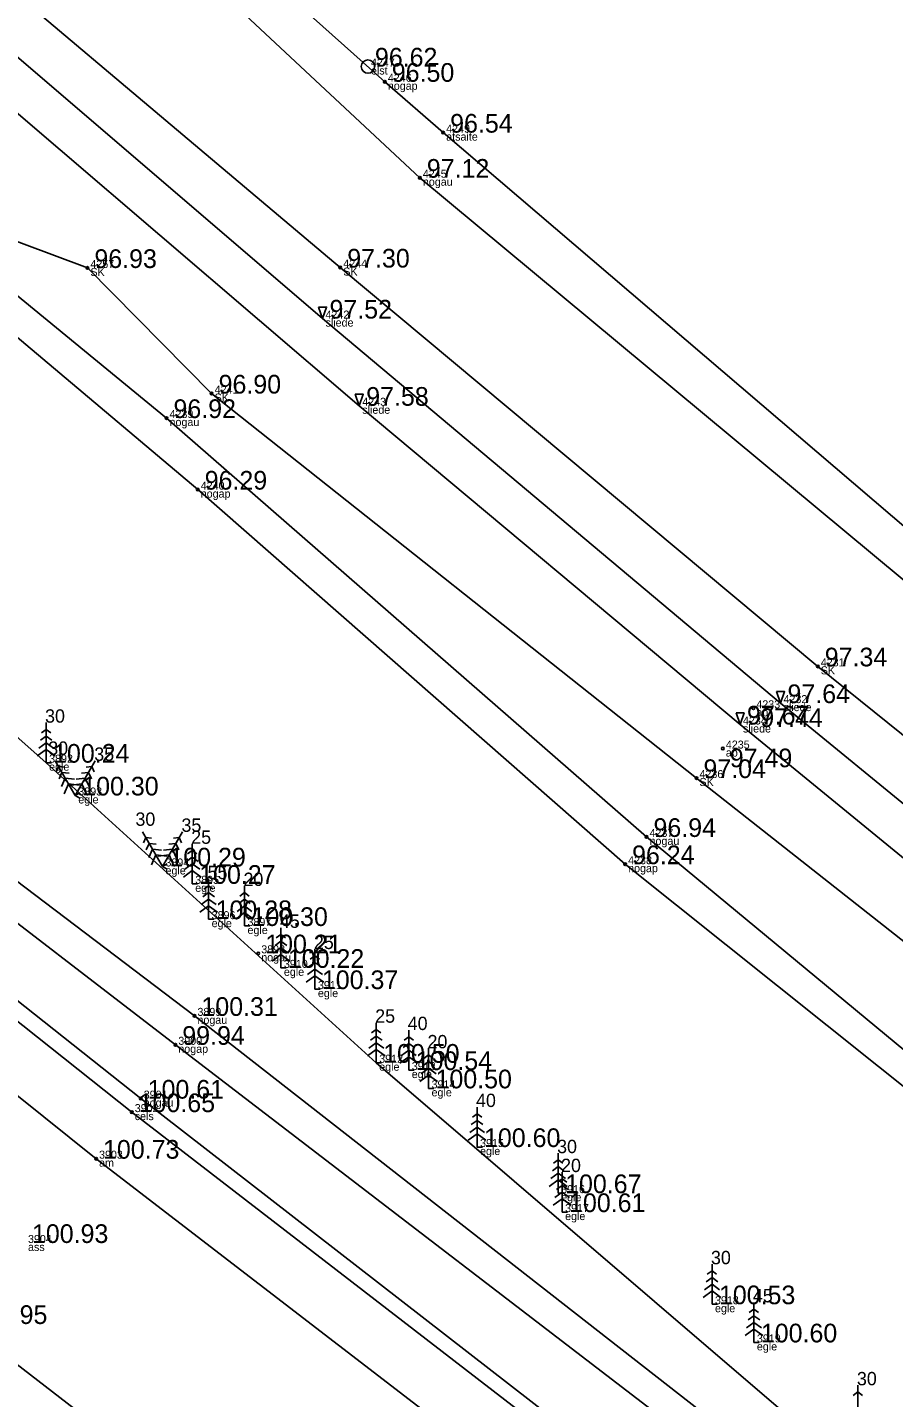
# Model space of a CAD drawing. Extents: x 614911 to 615803, y 262110 to 264311.
# Drawn here: x 615690.4 to 615722.9, y 264108 to 264159.4 of the extents above; entities that cross this region are included whole.
import ezdxf

# ---------------------------------------------------------------- set-up
doc = ezdxf.new("R2010")
doc.units = 0
for name, color, linetype in [('Level 1', 7, 'Continuous'), ('Level 18', 7, 'Continuous'), ('Level 31', 7, 'Continuous'), ('Level 37', 7, 'Continuous'), ('Level 53', 7, 'Continuous'), ('Level 54', 7, 'Continuous'), ('Level 57', 7, 'Continuous'), ('Level 58', 7, 'Continuous')]:
    doc.layers.add(name, color=color, linetype=linetype)

msp = doc.modelspace()

# ---------------------------------------------------------------- linework, layer by layer
at = {"layer": 'Level 1'}
for p, q in [((615691.136, 264133.05), (615690.96, 264132.922)), ((615691.136, 264133.3), (615691.136, 264131.8)), ((615691.136, 264133.05), (615691.31, 264132.922)), ((615691.136, 264132.55), (615690.858, 264132.346)), ((615691.136, 264132.8), (615690.92, 264132.642)), ((615691.136, 264132.8), (615691.352, 264132.642)), ((615691.136, 264132.55), (615691.414, 264132.346)), ((615691.136, 264132.3), (615690.804, 264132.056)), ((615691.136, 264132.3), (615691.47, 264132.056)), ((615691.48, 264131.87), (615692.23, 264130.571)), ((615692.98, 264131.87), (615692.23, 264130.571)), ((615691.136, 264131.8), (615691.336, 264131.8)), ((615691.605, 264131.654), (615691.517, 264131.455)), ((615691.605, 264131.654), (615691.82, 264131.63)), ((615691.73, 264131.437), (615691.622, 264131.192)), ((615691.73, 264131.437), (615691.996, 264131.408)), ((615692.73, 264131.437), (615692.464, 264131.408)), ((615692.855, 264131.654), (615692.639, 264131.631)), ((615692.73, 264131.437), (615692.838, 264131.192)), ((615692.855, 264131.654), (615692.942, 264131.456)), ((615691.855, 264131.221), (615691.716, 264130.905)), ((615691.98, 264131.004), (615691.814, 264130.627)), ((615691.855, 264131.221), (615692.198, 264131.183)), ((615691.98, 264131.004), (615692.391, 264130.96)), ((615692.48, 264131.004), (615692.07, 264130.959)), ((615692.605, 264131.221), (615692.262, 264131.183)), ((615692.48, 264131.004), (615692.647, 264130.626)), ((615692.605, 264131.221), (615692.744, 264130.905)), ((615692.23, 264130.571), (615692.403, 264130.671)), ((615692.23, 264130.571), (615692.403, 264130.471)), ((615694.748, 264129.209), (615695.498, 264127.91)), ((615694.873, 264128.993), (615694.785, 264128.794)), ((615694.873, 264128.993), (615695.088, 264128.969)), ((615694.998, 264128.776), (615694.89, 264128.531)), ((615694.998, 264128.776), (615695.264, 264128.747)), ((615696.248, 264129.209), (615695.498, 264127.91)), ((615695.998, 264128.776), (615695.732, 264128.747)), ((615696.123, 264128.993), (615695.907, 264128.97)), ((615695.998, 264128.776), (615696.106, 264128.531)), ((615696.123, 264128.993), (615696.21, 264128.795)), ((615696.614, 264128.759), (615696.614, 264127.259)), ((615695.123, 264128.56), (615694.984, 264128.244)), ((615695.248, 264128.343), (615695.082, 264127.966)), ((615695.123, 264128.56), (615695.466, 264128.522)), ((615695.248, 264128.343), (615695.659, 264128.299)), ((615695.748, 264128.343), (615695.338, 264128.298)), ((615695.873, 264128.56), (615695.53, 264128.522)), ((615695.748, 264128.343), (615695.915, 264127.965)), ((615695.873, 264128.56), (615696.012, 264128.244)), ((615696.614, 264128.259), (615696.398, 264128.101)), ((615696.614, 264128.509), (615696.438, 264128.381)), ((615696.614, 264128.509), (615696.788, 264128.381)), ((615696.614, 264128.259), (615696.83, 264128.101)), ((615695.498, 264127.91), (615695.671, 264128.01)), ((615695.498, 264127.91), (615695.671, 264127.81)), ((615696.614, 264127.759), (615696.282, 264127.515)), ((615696.614, 264128.009), (615696.336, 264127.805)), ((615696.614, 264128.009), (615696.892, 264127.805)), ((615696.614, 264127.759), (615696.948, 264127.515)), ((615696.614, 264127.259), (615696.814, 264127.259)), ((615697.228, 264127.435), (615697.228, 264125.935)), ((615697.228, 264126.935), (615697.012, 264126.777)), ((615697.228, 264127.185), (615697.052, 264127.057)), ((615697.228, 264127.185), (615697.402, 264127.057)), ((615697.228, 264126.935), (615697.444, 264126.777)), ((615698.573, 264126.929), (615698.397, 264126.801)), ((615698.573, 264127.179), (615698.573, 264125.679)), ((615698.573, 264126.929), (615698.747, 264126.801)), ((615697.228, 264126.435), (615696.896, 264126.191)), ((615697.228, 264126.685), (615696.95, 264126.481)), ((615697.228, 264126.685), (615697.506, 264126.481)), ((615697.228, 264126.435), (615697.562, 264126.191)), ((615698.573, 264126.179), (615698.241, 264125.935)), ((615698.573, 264126.429), (615698.295, 264126.225)), ((615698.573, 264126.679), (615698.357, 264126.521)), ((615698.573, 264126.679), (615698.789, 264126.521)), ((615698.573, 264126.429), (615698.851, 264126.225)), ((615698.573, 264126.179), (615698.907, 264125.935)), ((615697.228, 264125.935), (615697.428, 264125.935)), ((615698.573, 264125.679), (615698.773, 264125.679)), ((615699.938, 264125.36), (615699.762, 264125.232)), ((615699.938, 264125.61), (615699.938, 264124.11)), ((615699.938, 264125.36), (615700.112, 264125.232)), ((615699.938, 264124.86), (615699.66, 264124.656)), ((615699.938, 264125.11), (615699.722, 264124.952)), ((615699.938, 264125.11), (615700.154, 264124.952)), ((615699.938, 264124.86), (615700.216, 264124.656)), ((615701.213, 264124.814), (615701.213, 264123.314)), ((615699.938, 264124.61), (615699.606, 264124.366)), ((615699.938, 264124.61), (615700.272, 264124.366)), ((615701.213, 264124.314), (615700.997, 264124.156)), ((615701.213, 264124.564), (615701.037, 264124.436)), ((615701.213, 264124.564), (615701.387, 264124.436)), ((615701.213, 264124.314), (615701.429, 264124.156)), ((615699.938, 264124.11), (615700.138, 264124.11)), ((615701.213, 264123.814), (615700.881, 264123.57)), ((615701.213, 264124.064), (615700.935, 264123.86)), ((615701.213, 264124.064), (615701.491, 264123.86)), ((615701.213, 264123.814), (615701.547, 264123.57)), ((615701.213, 264123.314), (615701.413, 264123.314)), ((615703.511, 264121.554), (615703.295, 264121.396)), ((615703.511, 264121.804), (615703.335, 264121.676)), ((615703.511, 264122.054), (615703.511, 264120.554)), ((615703.511, 264121.804), (615703.685, 264121.676)), ((615703.511, 264121.554), (615703.727, 264121.396)), ((615704.73, 264121.779), (615704.73, 264120.279)), ((615703.511, 264121.054), (615703.179, 264120.81)), ((615703.511, 264121.304), (615703.233, 264121.1)), ((615703.511, 264121.304), (615703.789, 264121.1)), ((615703.511, 264121.054), (615703.845, 264120.81)), ((615704.73, 264121.279), (615704.514, 264121.121)), ((615704.73, 264121.529), (615704.554, 264121.401)), ((615704.73, 264121.529), (615704.904, 264121.401)), ((615704.73, 264121.279), (615704.946, 264121.121)), ((615705.473, 264121.094), (615705.473, 264119.594)), ((615703.511, 264120.554), (615703.711, 264120.554)), ((615704.73, 264120.779), (615704.398, 264120.535)), ((615704.73, 264121.029), (615704.452, 264120.825)), ((615704.73, 264121.029), (615705.008, 264120.825)), ((615704.73, 264120.779), (615705.064, 264120.535)), ((615705.473, 264120.594), (615705.257, 264120.436)), ((615705.473, 264120.844), (615705.297, 264120.716)), ((615705.473, 264120.844), (615705.647, 264120.716)), ((615705.473, 264120.594), (615705.689, 264120.436)), ((615704.73, 264120.279), (615704.93, 264120.279)), ((615705.473, 264120.094), (615705.141, 264119.85)), ((615705.473, 264120.344), (615705.195, 264120.14)), ((615705.473, 264120.344), (615705.751, 264120.14)), ((615705.473, 264120.094), (615705.807, 264119.85)), ((615705.473, 264119.594), (615705.673, 264119.594)), ((615707.291, 264118.644), (615707.115, 264118.516)), ((615707.291, 264118.894), (615707.291, 264117.394)), ((615707.291, 264118.644), (615707.465, 264118.516)), ((615707.291, 264118.144), (615707.013, 264117.94)), ((615707.291, 264118.394), (615707.075, 264118.236)), ((615707.291, 264118.394), (615707.507, 264118.236)), ((615707.291, 264118.144), (615707.569, 264117.94)), ((615707.291, 264117.894), (615706.959, 264117.65)), ((615707.291, 264117.894), (615707.625, 264117.65)), ((615707.291, 264117.394), (615707.491, 264117.394)), ((615710.331, 264117.165), (615710.331, 264115.665)), ((615710.331, 264116.665), (615710.115, 264116.507)), ((615710.331, 264116.915), (615710.155, 264116.787)), ((615710.331, 264116.915), (615710.505, 264116.787)), ((615710.331, 264116.665), (615710.547, 264116.507)), ((615710.479, 264116.456), (615710.479, 264114.956)), ((615710.331, 264116.165), (615709.999, 264115.921)), ((615710.331, 264116.415), (615710.053, 264116.211)), ((615710.479, 264115.956), (615710.263, 264115.798)), ((615710.479, 264116.206), (615710.303, 264116.078)), ((615710.331, 264116.415), (615710.609, 264116.211)), ((615710.331, 264116.165), (615710.665, 264115.921)), ((615710.479, 264116.206), (615710.653, 264116.078)), ((615710.479, 264115.956), (615710.695, 264115.798)), ((615710.479, 264115.456), (615710.147, 264115.212)), ((615710.479, 264115.706), (615710.201, 264115.502)), ((615710.331, 264115.665), (615710.531, 264115.665)), ((615710.479, 264115.706), (615710.757, 264115.502)), ((615710.479, 264115.456), (615710.813, 264115.212)), ((615710.479, 264114.956), (615710.679, 264114.956)), ((615716.098, 264113.002), (615716.098, 264111.502)), ((615716.098, 264112.502), (615715.882, 264112.344)), ((615716.098, 264112.752), (615715.922, 264112.624)), ((615716.098, 264112.752), (615716.272, 264112.624)), ((615716.098, 264112.502), (615716.314, 264112.344)), ((615716.098, 264112.002), (615715.766, 264111.758)), ((615716.098, 264112.252), (615715.82, 264112.048)), ((615716.098, 264112.252), (615716.376, 264112.048)), ((615716.098, 264112.002), (615716.432, 264111.758)), ((615716.098, 264111.502), (615716.298, 264111.502)), ((615717.669, 264111.322), (615717.493, 264111.194)), ((615717.669, 264111.572), (615717.669, 264110.072)), ((615717.669, 264111.322), (615717.843, 264111.194)), ((615717.669, 264110.822), (615717.391, 264110.618)), ((615717.669, 264111.072), (615717.453, 264110.914)), ((615717.669, 264111.072), (615717.885, 264110.914)), ((615717.669, 264110.822), (615717.947, 264110.618)), ((615717.669, 264110.572), (615717.337, 264110.328)), ((615717.669, 264110.572), (615718.003, 264110.328)), ((615717.669, 264110.072), (615717.869, 264110.072)), ((615721.57, 264108.214), (615721.394, 264108.086)), ((615721.57, 264108.464), (615721.57, 264106.964)), ((615721.57, 264108.214), (615721.744, 264108.086))]:
    msp.add_line(p, q, dxfattribs=at)
at = {"layer": 'Level 18'}
msp.add_circle((615703.201, 264157.893), 0.25, dxfattribs=at)
at = {"layer": 'Level 31'}
for points in [[(615550.836, 264303.699), (615565.947, 264286.87), (615580.435, 264272.627), (615620.447, 264233.205), (615638.898, 264215.233), (615657.591, 264198.466), (615675.473, 264182.627), (615703.834, 264157.321), (615706.022, 264155.415), (615724.24, 264139.85), (615743.993, 264123.553), (615763.286, 264108.956)], [(615762.569, 264108.432), (615743.376, 264122.276), (615723.221, 264138.687), (615705.147, 264153.725), (615674.877, 264181.955), (615656.951, 264197.747), (615637.976, 264214.014), (615619.221, 264231.816), (615602.006, 264248.823), (615581.186, 264269.584), (615564.897, 264285.757), (615549.808, 264302.584)], [(615540.752, 264293.153), (615554.871, 264276.489), (615571.152, 264259.742), (615591.296, 264239.745), (615608.637, 264222.837), (615628.706, 264203.767), (615646.768, 264187.421), (615664.713, 264171.246), (615679.702, 264157.791), (615695.65, 264144.718), (615713.644, 264129.017), (615734.176, 264112.026), (615754.636, 264096.634)], [(615753.478, 264095.562), (615733.7, 264111.337), (615712.842, 264127.996), (615696.82, 264142.035), (615679.383, 264156.731), (615663.464, 264170.411), (615645.861, 264186.034), (615627.735, 264202.684), (615607.548, 264221.434), (615590.341, 264238.61), (615571.816, 264257.419), (615555.77, 264271.235), (615553.667, 264275.682), (615546.609, 264281.236), (615539.858, 264291.16)], [(615744.764, 264081.359), (615732.887, 264089.943), (615715.889, 264102.764), (615694.682, 264119.208), (615676.974, 264133.244), (615650.72, 264155.552), (615629.606, 264174.135), (615612.305, 264190.628), (615596.307, 264206.969), (615581.341, 264223.238), (615571.304, 264233.709), (615558.243, 264246.987), (615542.242, 264265.322), (615529.994, 264284)], [(615573.297, 264235.218), (615582.765, 264223.901), (615598.169, 264208.795), (615613.95, 264192.439), (615631.402, 264176.068), (615651.799, 264157.165), (615678.305, 264134.819), (615695.98, 264121.225), (615717.243, 264104.936), (615734.373, 264091.846), (615746.465, 264082.76)], [(615748.571, 264085.022), (615736.423, 264094.22), (615719.121, 264107.166), (615703.511, 264120.554), (615691.136, 264131.8), (615678.521, 264143.006), (615664.052, 264155.366), (615649.085, 264167.868)], [(615652.699, 264158.282), (615678.791, 264135.883), (615696.697, 264122.31), (615717.87, 264105.783), (615735.585, 264093.051), (615747.497, 264083.99)]]:
    msp.add_lwpolyline(points, dxfattribs=at)
at = {"layer": 'Level 37'}
for points in [[(615761.079, 264103.167), (615740.608, 264118.87), (615720.064, 264135.41), (615702.164, 264150.358), (615683.412, 264166.162), (615670.618, 264177.317), (615652.713, 264193.863), (615634.786, 264210.699), (615620.941, 264223.967), (615615.966, 264228.972), (615599.176, 264245.886), (615578.012, 264266.798), (615562.423, 264283.045), (615547.324, 264299.857)], [(615759.565, 264101.106), (615739.143, 264117.266), (615718.667, 264134.033), (615701.498, 264148.445), (615682.756, 264164.518), (615669.543, 264176.126), (615651.347, 264192.511), (615633.272, 264209.191), (615614.204, 264227.4), (615597.285, 264244.019), (615576.358, 264265.082), (615560.633, 264281.446), (615545.346, 264297.738)], [(615544.24, 264296.658), (615559.48, 264280.438), (615575.312, 264263.924), (615595.914, 264243.146), (615613.083, 264226.335), (615632.332, 264207.923), (615650.408, 264191.231), (615668.49, 264174.989), (615684.179, 264161.185), (615702.875, 264145.178), (615717.148, 264133.231), (615738.189, 264116.022), (615758.45, 264099.985)], [(615540.752, 264293.153), (615550.108, 264282.114), (615552.773, 264283.226), (615557.41, 264278.457), (615573.64, 264261.965), (615593.655, 264241.56), (615611.026, 264224.494), (615630.543, 264205.827), (615648.416, 264189.194), (615666.454, 264173.12), (615670.636, 264169.646), (615672.409, 264164.575), (615679.702, 264157.791), (615684.212, 264153.509), (615692.685, 264150.342), (615697.341, 264145.636), (615715.517, 264131.224), (615736.783, 264114.465), (615756.444, 264098.349)], [(615526.871, 264279.709), (615557.508, 264246.916), (615570.946, 264232.844), (615580.588, 264222.695), (615595.945, 264206.676), (615612.011, 264190.126), (615629.214, 264173.64), (615650.344, 264154.99), (615676.59, 264132.802), (615694.345, 264118.703), (615715.543, 264102.359), (615732.654, 264089.574), (615744.576, 264080.858)], [(615743.178, 264079.076), (615731.345, 264087.792), (615714.316, 264100.575), (615693.008, 264116.957), (615675.219, 264131.222), (615649.561, 264152.667), (615627.765, 264171.974), (615611.182, 264188.292), (615594.351, 264205.525), (615579.137, 264221.33), (615569.398, 264231.353), (615556.134, 264245.272), (615540.03, 264262.148), (615525.148, 264277.969)], [(615625.063, 264106.562), (615623.229, 264104.588), (615622.747, 264105.634), (615621.37, 264105.71), (615619.131, 264107.71), (615616.734, 264111.901), (615616.748, 264121.153), (615617.254, 264127.034), (615619.687, 264135.318), (615625.708, 264142.666), (615632.784, 264145.968), (615640.605, 264144.932), (615648.422, 264143.136), (615670.375, 264124.985), (615688.06, 264110.762), (615709.564, 264094.167), (615727.03, 264081.038), (615738.779, 264072.364)]]:
    msp.add_lwpolyline(points, dxfattribs=at)
at = {"layer": 'Level 57'}
for centre in [(615703.834, 264157.321), (615706.022, 264155.415), (615705.147, 264153.725), (615692.685, 264150.342), (615702.164, 264150.358), (615697.341, 264145.636), (615695.65, 264144.718), (615696.82, 264142.035), (615720.064, 264135.41), (615717.648, 264133.838), (615716.505, 264132.329), (615715.517, 264131.224), (615713.644, 264129.017), (615712.842, 264127.996), (615699.089, 264124.654), (615696.697, 264122.31), (615695.98, 264121.225), (615694.682, 264119.208), (615694.345, 264118.703), (615693.008, 264116.957)]:
    msp.add_circle(centre, 0.05, dxfattribs=at)
at = {"layer": 'Level 58'}
for points in [[(615701.348, 264148.879), (615701.648, 264148.879), (615701.498, 264148.446)], [(615702.725, 264145.611), (615703.025, 264145.611), (615702.875, 264145.178)], [(615718.517, 264134.466), (615718.817, 264134.466), (615718.667, 264134.033)], [(615716.998, 264133.664), (615717.298, 264133.664), (615717.148, 264133.231)]]:
    msp.add_lwpolyline(points, close=True, dxfattribs=at)
for centre in [(615703.834, 264157.321), (615706.022, 264155.415), (615705.147, 264153.725), (615692.685, 264150.342), (615702.164, 264150.358), (615697.341, 264145.636), (615695.65, 264144.718), (615696.82, 264142.035), (615720.064, 264135.41), (615717.648, 264133.838), (615716.505, 264132.329), (615715.517, 264131.224), (615713.644, 264129.017), (615712.842, 264127.996), (615699.089, 264124.654), (615696.697, 264122.31), (615695.98, 264121.225), (615694.682, 264119.208), (615694.345, 264118.703), (615693.008, 264116.957)]:
    msp.add_circle(centre, 0.05, dxfattribs=at)

# ---------------------------------------------------------------- texts
at = {"layer": 'Level 1'}
for s, p in [(' 30', (615690.911, 264133.3)), (' 30', (615691.03, 264132.095)), (' 35', (615692.755, 264131.87)), (' 30', (615694.298, 264129.434)), (' 35', (615696.023, 264129.209)), (' 25', (615696.389, 264128.759)), (' 55', (615697.003, 264127.435)), (' 20', (615698.348, 264127.179)), (' 45', (615699.713, 264125.61)), (' 25', (615700.988, 264124.814)), (' 25', (615703.286, 264122.054)), (' 40', (615704.505, 264121.779)), (' 20', (615705.248, 264121.094)), (' 40', (615707.066, 264118.894)), (' 30', (615710.106, 264117.165)), (' 20', (615710.254, 264116.456)), (' 30', (615715.873, 264113.002)), (' 45', (615717.444, 264111.572)), (' 30', (615721.345, 264108.464))]:
    msp.add_text(s, height=0.5, dxfattribs=at).set_placement(p)
at = {"layer": 'Level 53'}
for s, p in [(' elst', (615703.201, 264157.593)), (' nogap', (615703.834, 264157.021)), (' atsaite', (615706.022, 264155.115)), (' nogau', (615705.147, 264153.425)), (' SK', (615692.685, 264150.042)), (' SK', (615702.164, 264150.058)), (' sliede', (615701.498, 264148.146)), (' SK', (615697.341, 264145.336)), (' sliede', (615702.875, 264144.878)), (' nogau', (615695.65, 264144.418)), (' nogap', (615696.82, 264141.735)), (' SK', (615720.064, 264135.11)), (' sliede', (615718.667, 264133.733)), (' ap', (615717.648, 264133.538)), (' sliede', (615717.148, 264132.931)), (' ap', (615716.505, 264132.029)), (' egle', (615691.136, 264131.5)), (' SK', (615715.517, 264130.924)), (' egle', (615692.23, 264130.271)), (' nogau', (615713.644, 264128.717)), (' egle', (615695.498, 264127.61)), (' nogap', (615712.842, 264127.696)), (' egle', (615696.614, 264126.959)), (' egle', (615697.228, 264125.635)), (' egle', (615698.573, 264125.379)), (' nogau', (615699.089, 264124.354)), (' egle', (615699.938, 264123.81)), (' egle', (615701.213, 264123.014)), (' nogau', (615696.697, 264122.01)), (' nogap', (615695.98, 264120.925)), (' egle', (615703.511, 264120.254)), (' egle', (615704.73, 264119.979)), (' egle', (615705.473, 264119.294)), (' nogau', (615694.682, 264118.908)), (' cels', (615694.345, 264118.403)), (' egle', (615707.291, 264117.094)), (' am', (615693.008, 264116.657)), (' egle', (615710.331, 264115.365)), (' egle', (615710.479, 264114.656)), (' ass', (615690.345, 264113.498)), (' egle', (615716.098, 264111.202)), (' egle', (615717.669, 264109.772))]:
    msp.add_text(s, height=0.3, dxfattribs=at).set_placement(p)
at = {"layer": 'Level 54'}
for s, p in [(' 4247', (615703.201, 264157.893)), (' 4246', (615703.834, 264157.321)), (' 4249', (615706.022, 264155.415)), (' 4245', (615705.147, 264153.725)), (' 4257', (615692.685, 264150.342)), (' 4244', (615702.164, 264150.358)), (' 4242', (615701.498, 264148.446)), (' 4241', (615697.341, 264145.636)), (' 4243', (615702.875, 264145.178)), (' 4239', (615695.65, 264144.718)), (' 4240', (615696.82, 264142.035)), (' 4231', (615720.064, 264135.41)), (' 4233', (615717.648, 264133.838)), (' 4232', (615718.667, 264134.033)), (' 4234', (615717.148, 264133.231)), (' 4235', (615716.505, 264132.329)), (' 3892', (615691.136, 264131.8)), (' 4236', (615715.517, 264131.224)), (' 3893', (615692.23, 264130.571)), (' 4237', (615713.644, 264129.017)), (' 4238', (615712.842, 264127.996)), (' 3894', (615695.498, 264127.91)), (' 3895', (615696.614, 264127.259)), (' 3896', (615697.228, 264125.935)), (' 3897', (615698.573, 264125.679)), (' 3898', (615699.089, 264124.654)), (' 3910', (615699.938, 264124.11)), (' 3911', (615701.213, 264123.314)), (' 3899', (615696.697, 264122.31)), (' 3900', (615695.98, 264121.225)), (' 3912', (615703.511, 264120.554)), (' 3913', (615704.73, 264120.279)), (' 3901', (615694.682, 264119.208)), (' 3914', (615705.473, 264119.594)), (' 3902', (615694.345, 264118.703)), (' 3915', (615707.291, 264117.394)), (' 3903', (615693.008, 264116.957)), (' 3916', (615710.331, 264115.665)), (' 3917', (615710.479, 264114.956)), (' 3904', (615690.345, 264113.798)), (' 3918', (615716.098, 264111.502)), (' 3919', (615717.669, 264110.072))]:
    msp.add_text(s, height=0.3, dxfattribs=at).set_placement(p)
at = {"layer": 'Level 58'}
for s, p in [(' 96.62', (615703.201, 264157.893)), (' 96.50', (615703.834, 264157.321)), (' 96.54', (615706.022, 264155.415)), (' 97.12', (615705.147, 264153.725)), (' 96.93', (615692.685, 264150.342)), (' 97.30', (615702.164, 264150.358)), (' 97.52', (615701.498, 264148.446)), (' 96.90', (615697.341, 264145.636)), (' 97.58', (615702.875, 264145.178)), (' 96.92', (615695.65, 264144.718)), (' 96.29', (615696.82, 264142.035)), (' 97.34', (615720.064, 264135.41)), (' 97.64', (615718.667, 264134.033)), (' 97.67', (615717.148, 264133.231)), (' 97.44', (615717.648, 264133.138)), (' 100.24', (615691.136, 264131.8)), (' 97.49', (615716.505, 264131.629)), (' 97.04', (615715.517, 264131.224)), (' 100.30', (615692.23, 264130.571)), (' 96.94', (615713.644, 264129.017)), (' 100.29', (615695.498, 264127.91)), (' 96.24', (615712.842, 264127.996)), (' 100.27', (615696.614, 264127.259)), (' 100.28', (615697.228, 264125.935)), (' 100.30', (615698.573, 264125.679)), (' 100.21', (615699.089, 264124.654)), (' 100.22', (615699.938, 264124.11)), (' 100.37', (615701.213, 264123.314)), (' 100.31', (615696.697, 264122.31)), (' 99.94', (615695.98, 264121.225)), (' 100.50', (615703.511, 264120.554)), (' 100.54', (615704.73, 264120.279)), (' 100.50', (615705.473, 264119.594)), (' 100.61', (615694.682, 264119.208)), (' 100.65', (615694.345, 264118.703)), (' 100.60', (615707.291, 264117.394)), (' 100.73', (615693.008, 264116.957)), (' 100.67', (615710.331, 264115.665)), (' 100.61', (615710.479, 264114.956)), (' 100.93', (615690.345, 264113.798)), (' 100.53', (615716.098, 264111.502)), (' 100.95', (615688.06, 264110.762)), (' 100.60', (615717.669, 264110.072))]:
    msp.add_text(s, height=0.7, dxfattribs=at).set_placement(p)

doc.saveas('drawing.dxf')
